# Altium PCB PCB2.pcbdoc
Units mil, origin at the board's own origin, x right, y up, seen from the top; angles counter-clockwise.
Board outline 3820.55 x 1645 mil, 2 copper layers (Top Layer, Bottom Layer); 41 components, 48 nets, 181 pads, 91 vias.
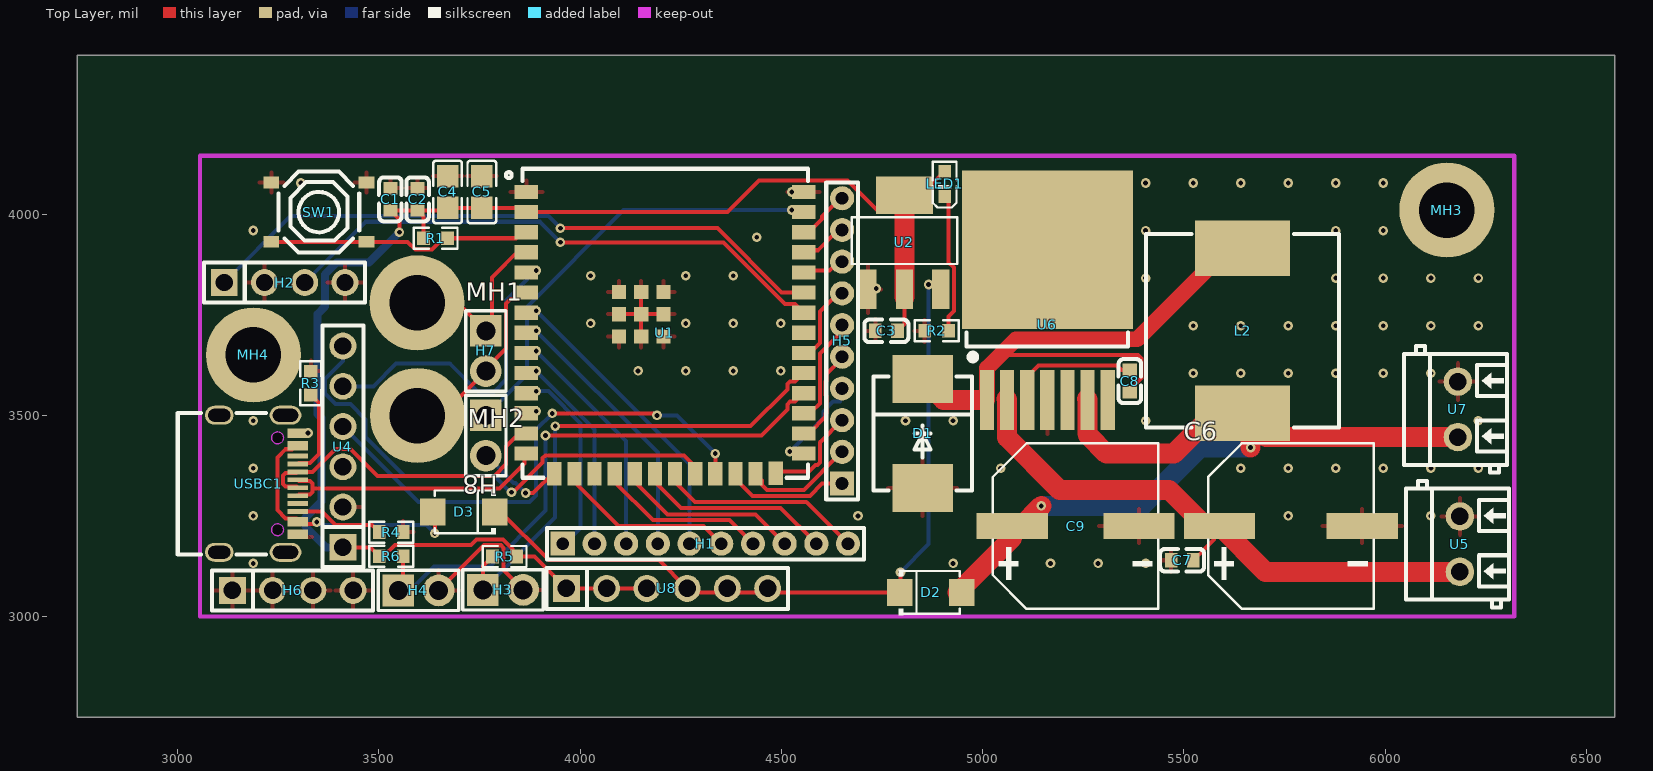
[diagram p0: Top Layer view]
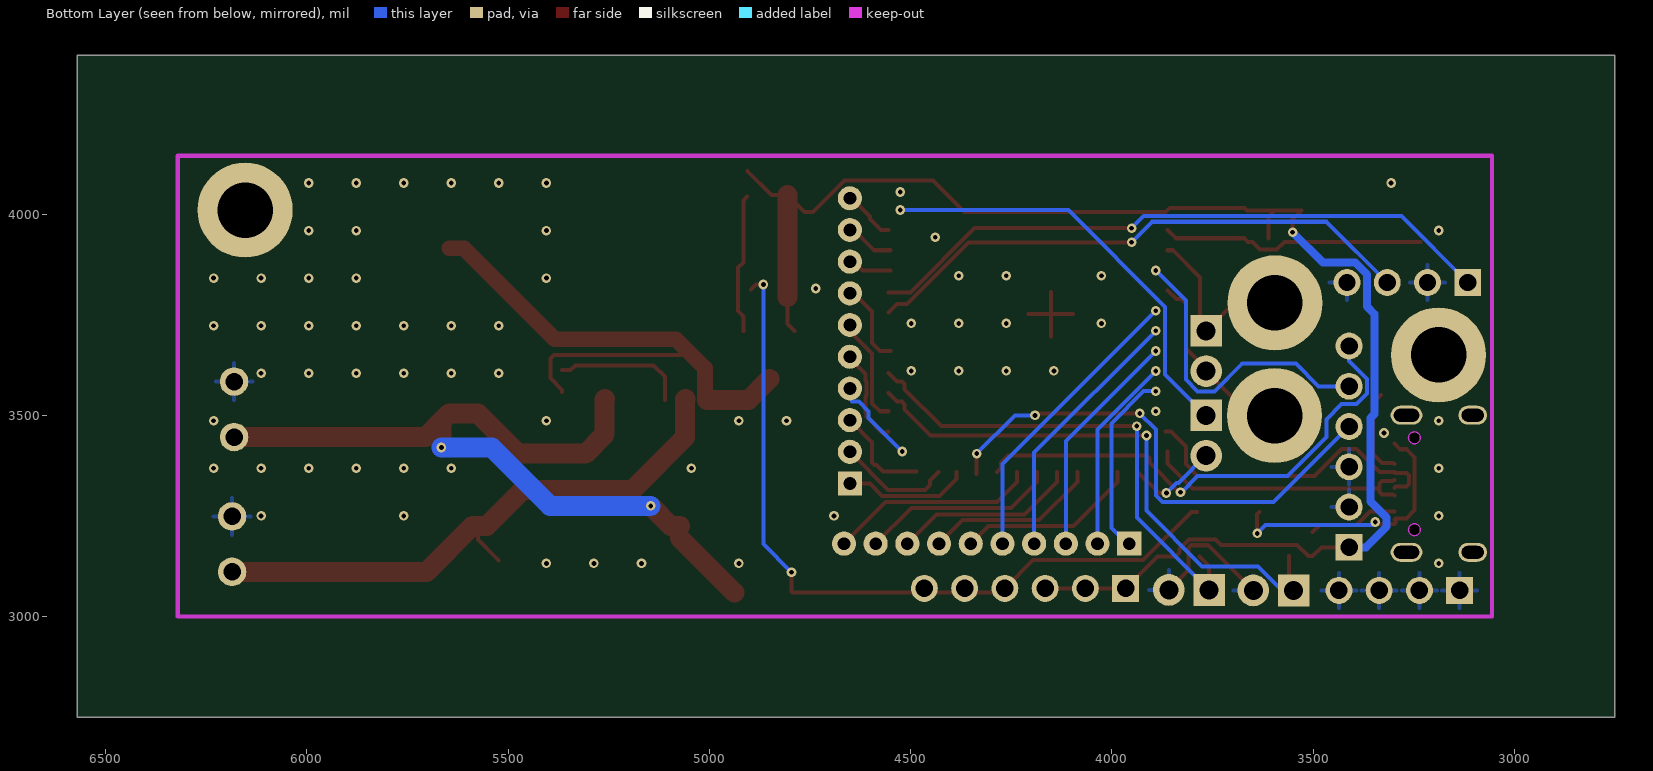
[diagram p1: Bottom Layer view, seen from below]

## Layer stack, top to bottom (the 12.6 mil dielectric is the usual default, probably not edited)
Top Layer: signal copper (thickness not stored)
Dielectric: dielectric 12.6, FR-4, Dk 4.8
Bottom Layer: signal copper (thickness not stored)

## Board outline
6570.55,2750 2750,2750 2750,4395 6570.55,4395

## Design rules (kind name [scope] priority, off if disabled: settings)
BoardOutlineClearance copperThickness1oz [All] p0: genericclearance=10 ignorepadtopadclearanceinfootprint=FALSE except(0: Arc-SplitContinuation Track-SplitContinuation SMDPad-SplitContinuation THPad-SplitContinuation Via-SplitContinuation Fill-SplitContinuation Poly-SplitContinuation Region-SplitContinuation Text-SplitContinuation; 6: Track-CutoutEdge SMDPad-CutoutEdge THPad-CutoutEdge Via-CutoutEdge Region-CutoutEdge; 11.8: Track-OutlineEdge SMDPad-OutlineEdge THPad-OutlineEdge Via-OutlineEdge Fill-OutlineEdge Region-OutlineEdge Poly-OutlineEdge Text-OutlineEdge Fill-CutoutEdge)
BoardOutlineClearance copperThickness2oz [All] p0: genericclearance=10 ignorepadtopadclearanceinfootprint=FALSE except(0: Arc-SplitContinuation Track-SplitContinuation SMDPad-SplitContinuation THPad-SplitContinuation Via-SplitContinuation Fill-SplitContinuation Poly-SplitContinuation Region-SplitContinuation Text-SplitContinuation; 6: Track-CutoutEdge SMDPad-CutoutEdge THPad-CutoutEdge Via-CutoutEdge Region-CutoutEdge; 11.8: Track-OutlineEdge SMDPad-OutlineEdge THPad-OutlineEdge Via-OutlineEdge Fill-OutlineEdge Region-OutlineEdge Poly-OutlineEdge Text-OutlineEdge Fill-CutoutEdge)
Clearance copperThickness1oz [(InNet('+3V') OR InNet('GND') OR InNet('$1N1546') OR InNet('LED_2') OR InNet('LED_1') OR InNet('$1N702') OR InNet('$1N2026') OR InNet('$1N2022') OR InNet('MIC_WS') OR InNet('SDA_1') OR InNet('USB_ESP_D-') OR InNet('USB_ESP_D+') OR InNet('RX') OR InNet('SCL_1') OR InNet('MIC_SDK') OR InNet('MIC_SCK') OR InNet('TX') OR InNet('+5V') OR InNet('USB_ESP_5V') OR InNet('+15V') OR InNet('$1N4882') OR InNet('$1N5299') OR InNet('TOUCH_1') OR InNet('TOUCH_2') OR InNet('IO7') OR InNet('IO15') OR InNet('IO16') OR InNet('IO17') OR InNet('IO18') OR InNet('IO46') OR InNet('IO10') OR InNet('IO11') OR InNet('IO12') OR InNet('IO13') OR InNet('IO47') OR InNet('IO48') OR InNet('IO45') OR InNet('IO0') OR InNet('IO35') OR InNet('IO36') OR InNet('BUTTON_2') OR InNet('BUTTON_1') OR InNet('IO39') OR InNet('IO40') OR InNet('RX0') OR InNet('TX0') OR InNet('IO2') OR InNet('5V_BUCK'))] p1: gap=7 ignorepadtopadclearanceinfootprint=FALSE except(4: Track-Track; 6: Track-SMDPad SMDPad-SMDPad Track-THPad SMDPad-THPad THPad-THPad Track-Via SMDPad-Via THPad-Via Via-Via SMDPad-Fill THPad-Fill Via-Fill Fill-Fill Track-Region SMDPad-Region THPad-Region Via-Region Region-Region Track-Poly SMDPad-Poly THPad-Poly Via-Poly Fill-Poly Region-Poly Poly-Poly Track-Text SMDPad-Text THPad-Text Via-Text Fill-Text Region-Text Poly-Text Text-Text; 6.9: Track-Hole SMDPad-Hole THPad-Hole Via-Hole Fill-Hole Region-Hole Poly-Hole Text-Hole Sheet-Hole; 11.8: Track-Fill Fill-Region Track-Sheet SMDPad-Sheet THPad-Sheet Via-Sheet Fill-Sheet Region-Sheet Poly-Sheet Text-Sheet)
Clearance copperThickness2oz [All] p1: gap=7 ignorepadtopadclearanceinfootprint=FALSE except(6: Track-SMDPad SMDPad-SMDPad Track-THPad SMDPad-THPad THPad-THPad Track-Via SMDPad-Via THPad-Via Via-Via SMDPad-Fill THPad-Fill Via-Fill Fill-Fill Track-Region SMDPad-Region THPad-Region Via-Region Region-Region Track-Poly SMDPad-Poly THPad-Poly Via-Poly Fill-Poly Region-Poly Poly-Poly Track-Text SMDPad-Text THPad-Text Via-Text Fill-Text Region-Text Poly-Text Text-Text; 6.9: Track-Hole SMDPad-Hole THPad-Hole Via-Hole Fill-Hole Region-Hole Poly-Hole Text-Hole Sheet-Hole; 8: Track-Track; 11.8: Track-Fill Fill-Region Track-Sheet SMDPad-Sheet THPad-Sheet Via-Sheet Fill-Sheet Region-Sheet Poly-Sheet Text-Sheet)
DiffPairsRouting differentialPair [All] p1: maxuncoupledlength=10 minlimit=6 maxlimit=6 mostfreqgap=6 toplayer_minwidth=5 toplayer_prefwidth=10 toplayer_maxwidth=100 bottomlayer_minwidth=5 bottomlayer_prefwidth=10 bottomlayer_maxwidth=100
PasteMaskExpansion pasteMaskExpansion [All] p1: expansion=0
PlaneConnect innerPlane [All] p1: planeconnectstyle=Relief reliefexpansion=20 reliefentries=4 reliefconductorwidth=10 reliefairgap=10
PolygonConnect copperRegion [All] p1: connectstyle=Relief reliefentries=4 reliefconductorwidth=10 polygonreliefangle="90 Angle" airgapwidth=10
RoutingVias viaSize [All] p1: viastyle="Through Hole" holewidth=12.0078 minholewidth=11.811 maxholewidth=248.0314 width=24.0158 minwidth=19.685 maxwidth=393.7008
SolderMaskExpansion solderMaskExpansion [All] p1: useseparateexpansions=TRUE expansion=2 expansionbottom=2
Width copperThickness1oz [All] p1: maxlimit=100 minlimit=5 preferedwidth=10
Width copperThickness2oz [All] p1: maxlimit=100 minlimit=8 preferedwidth=10

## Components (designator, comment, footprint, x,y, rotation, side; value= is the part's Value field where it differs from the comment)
C1 "CC0603KRX7R9BB104" C0603 3528.42,4036.76 r270 top
C2 "CL10A106KP8NNNC" C0603 3595.94,4036.76 r270 top
C3 "CL10A226MP8NUNE" C0603 4760.55,3710 r0 top
C4 "CL21B225KAFNNNE" C0805 3670.55,4055 r270 top
C5 "CL21B225KAFNNNE" C0805 3755.55,4055 r270 top
C6 "VMME1001H181MV" CAP-SMD_BD10.0-L10.3-W10.3-FD 5765.55,3225 r0 top
C7 "CC0603KRX7R9BB104" C0603 5495.55,3140 r0 top
C8 "CC0603KRX7R9BB103" C0603 5365.55,3585 r90 top
C9 "RVT1H271M1010" CAP-SMD_BD10.0-L10.3-W10.3-FD-1 5230.55,3225 r0 top
D1 "B540C-13-F" SMC_L7.1-W6.2-LS8.1-RD 4850.55,3455 r270 top
D2 "S2MF_C908416" SMAF_L3.5-W2.6-LS4.7-RD 4870.55,3060 r0 top
D3 "S2MF_C908416" SMAF_L3.5-W2.6-LS4.7-RD 3710.55,3260 r180 top
H1 "HX PZ2.0-1x10P ZZ" HDR-TH_10P-P2.00-V-M-1 4310.96,3181.24 r0 top
H2 "PZ254V-11-04P" HDR-TH_4P-P2.54-V-M 3265.55,3830 r0 top
H3 "PZ254V-11-02P" HDR-TH_2P-P2.54-V-M 3808.09,3066.24 r0 top
H4 "PZ254V-11-02P" HDR-TH_2P-P2.54-V-M 3598.09,3064.95 r0 top
H5 "HX PZ2.0-1x10P ZZ" HDR-TH_10P-P2.00-V-M-1 4650.55,3685 r90 top
H6 "PZ254V-11-04P" HDR-TH_4P-P2.54-V-M 3285.55,3065 r0 top
H7 "PZ254V-11-02P" HDR-TH_2P-P2.54-V-M 3765.55,3660 r270 top
H8 "PZ254V-11-02P" HDR-TH_2P-P2.54-V-M 3765.55,3450 r270 top
L2 "MSS1210-334KED" IND-SMD_L12.0-W12.0_SLH1207S100MTT 5645.55,3710 r90 top
LED1 "XL-1608UGC-04" LED0603-RD_GREEN 4905.55,4075 r90 top
MH1 "M3_Hole" M3_Hole 3594.66,3779.44 r0 top
MH2 "M3_Hole" M3_Hole 3595.57,3499.44 r0 top
MH3 "M3_Hole" M3_Hole 6153.11,4010.04 r0 top
MH4 "M3_Hole" M3_Hole 3188.11,3650.04 r0 top
R1 "RC0603FR-0710KL" R0603 3640.55,3940 r180 top
R2 "RC0603FR-07330RL" R0603 4885.55,3710 r0 top
R3 "RC0603FR-075K1L" R0603 3330.55,3580 r90 top
R4 "RC0603FR-075K1L" R0603 3530.55,3210 r180 top
R5 "RC0603FR-0710KL" R0603 3811.88,3149.3 r0 top
R6 "RC0603FR-0710KL" R0603 3530.55,3150 r180 top
SW1 "TS-1187A-B-A-B" SW-SMD_4P-L5.1-W5.1-P3.70-LS6.5-TL_H1.5 3350.55,4005 r180 top
U1 "ESP32-S3-WROOM-1U-N16R2" WIRELM-SMD_ESP32-S3-WROOM-1U 4210.55,3705 r0 top
U2 "AMS1117-3.3_C6186" SOT-223-3_L6.5-W3.4-P2.30-LS7.0-BR 4805.55,3930 r270 top
U4 "HB-PH3-25416PB2GOP" HDR-TH_6P-P2.54-V-M 3410.4,3422.24 r90 top
U5 "DB301V-3.5-2P-GN-S" CONN-TH_DB301V-3.5-2P-GN 6185.55,3180 r90 top
U6 "LM2678SX-5.0/NOPB" TO-263-7_L10.2-W8.6-P1.27-LS14.4-TL 5160.55,3725 r90 top
U7 "DB301V-3.5-2P-GN-S" CONN-TH_DB301V-3.5-2P-GN 6180.55,3515 r90 top
U8 "HB-PH3-25416PB2GOP" HDR-TH_6P-P2.54-V-M 4215.55,3070 r0 top
USBC1 "TYPE-C-31-M-12" USB-C_SMD-TYPE-C-31-M-12 3200.55,3330 r270 top

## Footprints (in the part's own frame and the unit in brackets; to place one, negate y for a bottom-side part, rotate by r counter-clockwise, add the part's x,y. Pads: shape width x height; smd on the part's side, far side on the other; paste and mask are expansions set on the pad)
C0603 [mm]
  rect 0.8x0.9 smd: 1(-0.7,0) 2(0.7,0)
  silkscreen extent -1.39,-0.71 1.39,0.71
C0805 [mm]
  rect 1.41x1.35 smd: 1(-1,0) 2(1,0)
  silkscreen extent -1.96,-0.9 1.96,0.9
CAP-SMD_BD10.0-L10.3-W10.3-FD [mm]
  rect 4.5x1.65 smd: 1(-4.5,0) 2(4.5,0)
  silkscreen extent -5.23,-5.23 5.23,5.23
CAP-SMD_BD10.0-L10.3-W10.3-FD-1 [mm]
  rect 4.5x1.65 smd: 1(-4,0) 2(4,0)
  silkscreen extent -5.23,-5.23 5.23,5.23
CONN-TH_DB301V-3.5-2P-GN [mm]
  round 1.8 hole 1.1: 1(-1.75,0) 2(1.75,0)
  silkscreen extent -4,-3.1 4,3.4
HDR-TH_2P-P2.54-V-M [mm]
  rect 2x2 hole 1.2: 1(-1.27,0)
  round 2 hole 1.2: 2(1.27,0)
  silkscreen extent -2.54,-1.27 2.54,1.27
HDR-TH_4P-P2.54-V-M [mm]
  rect 1.7x1.7 hole 1.1: 1(-3.81,0)
  round 1.7 hole 1.1: 2(-1.27,0) 3(1.27,0) 4(3.81,0)
  silkscreen extent -5.08,-1.27 5.08,1.27
HDR-TH_6P-P2.54-V-M [mm]
  rect 1.7x1.7 hole 1.1: 1(-6.35,0)
  round 1.7 hole 1.1: 2(-3.81,0) 3(-1.27,0) 4(1.27,0) 5(3.81,0) 6(6.35,0)
  silkscreen extent -7.6,-1.3 7.65,1.3
HDR-TH_10P-P2.00-V-M-1 [mil]
  rect 60x60 hole 31.5: 1(-354.33,0)
  round 60 hole 31.5: 2(-275.59,0) 3(-196.85,0) 4(-118.11,0) 5(-39.37,0) 6(39.37,0) 7(118.11,0) 8(196.85,0) 9(275.59,0) 10(354.33,0)
  silkscreen extent -394,-39 394,39
IND-SMD_L12.0-W12.0_SLH1207S100MTT [mm]
  rect 3.5x6 smd: 1(5.207,0) 2(-5.207,0)
  silkscreen extent -6.1,-6.1 6.1,6.1
LED0603-RD_GREEN [mm]
  rect 0.8x0.8 smd: 1(-0.799,-0.003) 2(0.799,0.003)
  silkscreen extent -1.49,-0.75 1.39,0.76
M3_Hole [mm]
  round 6 hole 3.5: 1(0,0)
R0603 [mil]
  rect 31.75x34.02 smd: 1(-29.66,0) 2(29.66,0)
  silkscreen extent -55,-26 55,26
SMAF_L3.5-W2.6-LS4.7-RD [mm]
  rect 1.6x1.7 smd: 1(-1.96,0) 2(1.96,0)
  silkscreen extent -2.01,-1.43 1.83,1.42
SMC_L7.1-W6.2-LS8.1-RD [mm]
  rect 3.03x3.82 smd: 1(-3.435,0) 2(3.435,0)
  silkscreen extent -3.6,-3.11 3.6,3.11
SOT-223-3_L6.5-W3.4-P2.30-LS7.0-BR [mm]
  rect 2.5x1.1 smd: 1(2.97,-2.3) 2(2.97,0) 3(2.97,2.3)
  rect 2.34x3.6 smd: 4(-2.97,0)
  silkscreen extent -1.57,-3.33 1.37,3.33
SW-SMD_4P-L5.1-W5.1-P3.70-LS6.5-TL_H1.5 [mm]
  rect 1x0.75 smd: 1(-3,1.875) 2(3,1.875) 3(-3,-1.875) 4(3,-1.875)
  silkscreen extent -2.55,-2.55 2.55,2.55
TO-263-7_L10.2-W8.6-P1.27-LS14.4-TL [mm]
  rect 3.81x0.9 smd: 1(-4.743,3.81) 2(-4.743,2.54) 3(-4.743,1.27) 4(-4.743,0) 5(-4.743,-1.27) 6(-4.743,-2.54) 7(-4.743,-3.81)
  rect 10x10.8 smd: 8(4.743,0)
  silkscreen extent -2.23,-5.09 -0.49,5.11
USB-C_SMD-TYPE-C-31-M-12 [mm]
  oval 1.2x2 hole 0.8 slot 1.6 at 90 deg: 0(-4.325,1.706) 1(4.325,1.706)
  oval 1.2x1.8 hole 0.8 slot 1.4 at 90 deg: 2(4.325,-2.474) 3(-4.325,-2.474)
  rect 0.3x1.3 smd: A1(-3.35,2.474) A4(-2.55,2.474) A5(-1.25,2.474) A6(-0.25,2.474) A7(0.25,2.474) A8(1.25,2.474) A9(2.55,2.474) A12(3.35,2.474) B1(3.05,2.474) B4(2.25,2.474) B5(1.75,2.474) B6(0.75,2.474) B7(-0.75,2.474) B8(-1.75,2.474) B9(-2.25,2.474) B12(-3.05,2.474)
  Board Outline Layer circle w0.005: c-2.9,1.206 r0.375
  Board Outline Layer circle w0.005: c2.9,1.206 r0.375
  Board Outline Layer region: -2.9,1.581 -2.737,1.544 -2.607,1.439 -2.534,1.289 -2.534,1.122 -2.607,0.972 -2.737,0.868 -2.9,0.831 -2.9,0.831 -3.063,0.868 -3.193,0.972 -3.266,1.122 -3.266,1.289 -3.193,1.439 -3.063,1.544 -2.9,1.581
  Board Outline Layer region: 2.9,1.581 3.063,1.544 3.193,1.439 3.266,1.289 3.266,1.122 3.193,0.972 3.063,0.868 2.9,0.831 2.9,0.831 2.737,0.868 2.607,0.972 2.534,1.122 2.534,1.289 2.607,1.439 2.737,1.544 2.9,1.581
  Multi-Layer board cut-out: -2.9,1.581 -2.737,1.544 -2.607,1.439 -2.534,1.289 -2.534,1.122 -2.607,0.972 -2.737,0.868 -2.9,0.831 -2.9,0.831 -3.063,0.868 -3.193,0.972 -3.266,1.122 -3.266,1.289 -3.193,1.439 -3.063,1.544 -2.9,1.581
  Multi-Layer board cut-out: 2.9,1.581 3.063,1.544 3.193,1.439 3.266,1.289 3.266,1.122 3.193,0.972 3.063,0.868 2.9,0.831 2.9,0.831 2.737,0.868 2.607,0.972 2.534,1.122 2.534,1.289 2.607,1.439 2.737,1.544 2.9,1.581
  silkscreen extent -4.47,-5.09 4.47,0.49
WIRELM-SMD_ESP32-S3-WROOM-1U [mm]
  rect 1.5x0.9 smd: 1(-8.75,8.895) 2(-8.75,7.625) 3(-8.75,6.355) 4(-8.75,5.085) 5(-8.75,3.815) 6(-8.75,2.545) 7(-8.75,1.275) 8(-8.75,0.005) 9(-8.75,-1.265) 10(-8.75,-2.535) 11(-8.75,-3.805) 12(-8.75,-5.075) 13(-8.75,-6.345) 14(-8.75,-7.615) 27(8.75,-7.615) 28(8.75,-6.345) 29(8.75,-5.075) 30(8.75,-3.805) 31(8.75,-2.535) 32(8.75,-1.265) 33(8.75,0.005) 34(8.75,1.275) 35(8.75,2.545) 36(8.75,3.815) 37(8.75,5.085) 38(8.75,6.355) 39(8.75,7.625) 40(8.75,8.895)
  rect 0.9x1.5 smd: 15(-6.985,-8.895) 16(-5.715,-8.895) 17(-4.445,-8.895) 18(-3.175,-8.895) 19(-1.905,-8.895) 20(-0.635,-8.895) 21(0.635,-8.895) 22(1.905,-8.895) 23(3.175,-8.895) 24(4.445,-8.895) 25(5.715,-8.895) 26(6.985,-8.865)
  rect 0.9x0.9 smd: 41(-2.9,-0.225) 41(-2.9,1.175) 41(-2.9,2.575) 41(-1.5,-0.225) 41(-1.5,1.175) 41(-1.5,2.575) 41(-0.1,-0.225) 41(-0.1,1.175) 41(-0.1,2.575)
  silkscreen extent -10.04,-9.14 9.02,10.36

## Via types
v1: diameter 24.02, hole 12.01, Top Layer to Bottom Layer, 91 vias

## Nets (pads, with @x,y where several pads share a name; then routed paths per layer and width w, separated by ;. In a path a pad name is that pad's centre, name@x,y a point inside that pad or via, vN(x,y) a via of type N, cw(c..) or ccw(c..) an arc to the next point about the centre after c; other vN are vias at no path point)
5V_BUCK: C9.1 D2.2 L2.2 U6.6 U7.1 | length 2024
  Top Layer w50: D2.2@4937.72,3060 C9.1@5073.07,3195.35 ; C9.1 5095.55,3225 v1(5145.55,3275) ; U6.6@5259.34,3540.43 5260.64,3539.13 5260.64,3454.91 5261.85,3453.7 5261.85,3450.42 5307.27,3405 5474.84,3405 5574.84,3505 L2.2 L2.2@5665.55,3485 ; v1(5665.55,3420) L2.2@5665.55,3485 ; U7.1 5704.45,3446.11 L2.2@5665.55,3485
  Bottom Layer w50: v1(5145.55,3275) 5395.55,3275 5540.55,3420 v1(5665.55,3420)
$1N702: R1.1 SW1.1 SW1.2 U1.3 | length 656.5
  Top Layer w10: SW1.2 SW1.1 3571.29,3931.18 3590.47,3912.01 3631.32,3912.01 3650.49,3931.18 3661.39,3931.18 R1.1 3840.87,3940 U1.3@3861.06,3960.2
$1N1546: LED1.1 R2.2 | length 348.7
  Top Layer w10: LED1.1 4915.21,4034 4915.21,3880.36 4928.74,3866.84 4928.74,3759.31 4915.21,3745.78 R2.2
$1N2022: R4.2 USBC1.B5 | length 224.1
  Top Layer w10: USBC1.B5 3358.68,3261.1 3391.99,3227.79 3483.1,3227.79 R4.2
$1N2026: R3.1 USBC1.A5 | length 217.2
  Top Layer w10: USBC1.A5 3300.76,3382.01 3328.1,3382.01 3350.55,3404.46 3350.55,3530.34 R3.1
$1N4882: C8.2 U6.3 | length 329.6
  Top Layer w10: U6.3 5110.55,3596.51 5138.29,3624.24 5332.82,3624.24 5344.5,3612.56 C8.2
$1N5299: C8.1 D1.1 L2.1 U6.1 | length 1443.2
  Top Layer w10: 5064.05,3650 5385.55,3650 5394.25,3641.3 5394.25,3592.26 5365.55,3563.56 C8.1
  Top Layer w39.4: U6.1 U6.1 5010.63,3617.37 5082.47,3689.21 5383.79,3689.21 5609.58,3915 L2.1
  Top Layer w50: D1.1 4902.53,3538.26 U6.1@5005.33,3538.26
+3V: C1.2 C2.2 C3.2 C4.2 C5.2 LED1.2 R1.2 R5.2 R6.2 U1.2 U2.2 U2.4 U4.1 U8.1 U8.2 U8.3 | length 3816.3
  Top Layer w10: U4.1@3395.4,3172.24 3478.65,3172.24 R6.2 3511.8,3150 3539.79,3177.99 3728.45,3177.99 3741.77,3191.31 3808.45,3191.31 3831.54,3168.22 3831.54,3159.3 R5.2 3886.25,3149.3 U8.1 U8.2 U8.3 ; v1(3550.55,3955) 3550.55,3987.06 C1.2 C2.2 ; R1.2 3610.89,3994.25 C2.2 ; U1.2@3861.06,4010.2 3855.63,4015.63 C5.2 C4.2 3664.12,4009.2 C2.2 ; U1.2 4365.75,4005.2 4444.45,4083.9 4663.95,4083.9 4742.65,4005.2 4763.82,4005.2 U2.4 4845.87,4046.93 LED1.2 ; C3.2 4805.55,3727.44 U2.2@4805.55,3794.21
  Top Layer w50: U2.2@4805.55,3794.21 U2.2 U2.4
  Bottom Layer w20: U4.1 3368.73,3172.24 3317.56,3223.41 3317.56,3246.59 3357.15,3286.18 3357.15,3493.41 3346.94,3503.62 3346.94,3751.38 3366.1,3770.55 3366.1,3850.48 3395.07,3879.45 3475,3879.45 v1(3550.55,3955)
+5V: D2.1 D3.1 U2.3 U8.4 U8.5 U8.6 | length 1918.9
  Top Layer w10: D3.1 3802.33,3260 3922.08,3140.25 4195.3,3140.25 U8.4 4275.55,3060 D2.1 4795.55,3062.16 v1(4795.55,3110) ; v1(4865.55,3825) 4884.18,3825 U2.3
  Bottom Layer w10: v1(4795.55,3110) 4865.55,3180 v1(4865.55,3825)
+15V: C6.1 C7.2 U5.1 U6.2 | length 1465.6
  Top Layer w10: C7.2 5574.79,3191.68 C6.1@5574.79,3225
  Top Layer w50: U6.2@5059.34,3540.43 5060.64,3539.13 5060.64,3444.91 5190.55,3315 5462.91,3315 5552.91,3225 5574.79,3225 C6.1 5702.29,3111.11 U5.1
BUTTON_1: H3.1 R5.1 U1.31 | length 1253.9
  Top Layer w10: H3.1 3758.09,3125.18 R5.1 ; v1(3937.79,3473.22) 4423.07,3473.22 4514.53,3564.68 4514.53,3577.46 4520.97,3583.9 4533.74,3583.9 U1.31
  Bottom Layer w10: H3.1 3937.79,3245.93 v1(3937.79,3473.22)
BUTTON_2: H4.1 R6.1 U1.30 | length 1417.1
  Top Layer w10: H4.1 3560.21,3077.07 R6.1 ; v1(3913.58,3450) 4449.85,3450 4514.53,3514.68 4514.53,3527.46 4520.97,3533.9 4533.74,3533.9 U1.30
  Bottom Layer w10: H4.1 3576.88,3064.95 3636.94,3125 3775.55,3125 3913.58,3263.03 v1(3913.58,3450)
GND: C1.1 C2.1 C3.1 C4.1 C5.1 C6.2 C7.1 C9.2 D1.2 H2.2 H2.4 H3.2 H4.2 H6.1 H6.2 H6.3 H6.4 R2.1 R3.2 R4.1 SW1.3 SW1.4 U1.1 U1.40 U1.41 U2.1 U4.2 U4.3 U5.2 U6.4 U7.2 USBC1.A1 USBC1.A12 USBC1.B1 USBC1.B12 | length 555.6
  Top Layer w10: H4.2 3760.44,3177.29 3802.64,3177.29 3809.08,3170.86 3809.08,3115.25 H3.2 ; U1.41@4096.37,3751.26 U1.41@4151.49,3751.26 ; U1.41@4151.49,3696.14 U1.41@4151.49,3751.26 ; U1.41@4151.49,3806.38 U1.41@4151.49,3751.26 ; U1.41@4206.61,3751.26 U1.41@4151.49,3751.26
  other v1: 3187.76,3132.21 4926.4,3132.21 5168.5,3132.21 5286.61,3132.21 5404.72,3132.21 3187.76,3250.32 4690.18,3250.32 5759.05,3250.32 6113.38,3250.32 3187.76,3368.43 5044.51,3368.43 5640.94,3368.43 5759.05,3368.43 5877.16,3368.43 5995.27,3368.43 6113.38,3368.43 6231.49,3368.43 3323.55,3455.98 3187.76,3486.54 4808.29,3486.54 4926.4,3486.54 5404.72,3486.54 6231.49,3486.54 5522.83,3604.65 5640.94,3604.65 5759.05,3604.65 5877.16,3604.65 5995.27,3604.65 6113.38,3604.65 4143.88,3610.43 4261.99,3610.43 4380.1,3610.43 4498.21,3610.43 5522.83,3722.76 5640.94,3722.76 5759.05,3722.76 5877.16,3722.76 5995.27,3722.76 6113.38,3722.76 6231.49,3722.76 4025.77,3728.54 4261.99,3728.54 4380.1,3728.54 4498.21,3728.54 4735.55,3815 5404.72,3840.87 5877.16,3840.87 5995.27,3840.87 6113.38,3840.87 6231.49,3840.87 4025.77,3846.65 4261.99,3846.65 4380.1,3846.65 4438.38,3942.41 3187.76,3959.3 5404.72,3958.98 5877.16,3958.98 5995.27,3958.98 4525.55,4055 3305.87,4077.41 5404.72,4077.09 5522.83,4077.09 5640.94,4077.09 5759.05,4077.09 5877.16,4077.09 5995.27,4077.09
IO0: H5.4 U1.27 | length 223.1
  Bottom Layer w10: v1(4520.55,3410) 4604.57,3494.02 4604.57,3510.13 4628.58,3534.13 4644.69,3534.13 4645.55,3535 H5.4@4645.55,3571.89
IO2: H5.10 U1.38 | length 134.1
  Top Layer w10: U1.38@4555.04,3960.2 4572.82,3960.2 4600.55,3987.93 4600.55,3994.33 H5.10@4650.55,4044.33
IO7: H1.5 U1.7 | length 736.6
  Bottom Layer w10: v1(3890.55,3760) 4271.59,3378.96 H1.5
IO10: H1.7 U1.18 | length 432
  Top Layer w10: U1.18@4085.55,3359.8 4085.55,3335 4180.55,3240 4370.31,3240 H1.7
IO11: H1.8 U1.19 | length 460.8
  Top Layer w10: U1.19@4135.55,3359.8 4135.55,3335 4216.54,3254.02 4435.03,3254.02 H1.8
IO12: H1.9 U1.20 | length 489.5
  Top Layer w10: U1.20@4185.55,3359.8 4185.55,3335 4250.55,3270 4497.79,3270 H1.9
IO13: H1.10 U1.21 | length 518.2
  Top Layer w10: U1.21@4235.55,3359.8 4235.55,3335 4285.55,3285 4561.53,3285 H1.10
IO15: H1.4 U1.8 | length 654
  Bottom Layer w10: v1(3890.55,3710) 4192.85,3407.7 H1.4
IO16: H1.3 U1.9 | length 571.4
  Bottom Layer w10: v1(3890.55,3660) 4114.11,3436.44 H1.3
IO17: H1.2 U1.10 | length 488.7
  Bottom Layer w10: v1(3890.55,3610) 4035.37,3465.18 H1.2
IO18: H1.1 U1.11 | length 463.1
  Bottom Layer w10: v1(3890.55,3560) 3920.73,3560 4000.55,3480.18 4000.55,3220.16 3961.63,3181.24 H1.1
IO35: H5.5 U1.28 | length 239.6
  Top Layer w10: U1.28@4555.04,3460.2 4557.54,3457.7 4570.32,3457.7 4609.57,3496.94 4609.57,3505.13 4612.07,3507.63 4612.07,3547.41 4609.57,3549.91 4609.57,3583.87 4612.07,3586.37 4612.07,3602.15 4650.55,3640.63 H5.5
IO36: H5.6 U1.29 | length 270.9
  Top Layer w10: U1.29@4555.04,3510.2 4575.75,3510.2 4595.55,3530 4595.55,3653.59 4650.55,3708.59 H5.6@4650.55,3729.37
IO39: H5.7 U1.32 | length 202.5
  Top Layer w10: U1.32@4550.04,3660.2 4575.75,3660.2 4595.55,3680 4595.55,3758.11 H5.7@4645.55,3808.11
IO40: U1.33
IO45: H5.3 U1.26 | length 247.1
  Top Layer w10: U1.26@4485.55,3360.99 4568.61,3360.99 4584.12,3376.49 4589.12,3376.49 4595.55,3382.93 4595.55,3433.15 H5.3
IO46: H1.6 U1.16 | length 453.3
  Top Layer w10: U1.16@3985.55,3359.8 3985.55,3335 4095.55,3225 4306.57,3225 H1.6
IO47: H5.1 U1.24 | length 312.9
  Top Layer w10: U1.24@4385.55,3359.8 4385.55,3342.03 4427.58,3300 4570.55,3300 4601.22,3330.67 H5.1
IO48: H5.2 U1.25 | length 287
  Top Layer w10: U1.25@4430.55,3359.8 4451.85,3338.51 4451.85,3326.91 4463.76,3315 4555.55,3315 4645.55,3405 H5.2@4645.55,3414.41
LED_1: H2.1 U1.35 | length 1586.5
  Top Layer w10: v1(3950.55,3965) 4340.55,3965 4500.36,3805.2 U1.35
  Bottom Layer w10: H2.1 3280.55,3995 3920.55,3995 v1(3950.55,3965)
LED_2: H2.3 U1.34 | length 1395.6
  Top Layer w10: v1(3950.55,3930) 4355.73,3930 4509.24,3776.49 4533.74,3776.49 U1.34
  Bottom Layer w10: H2.3 3466.54,3980.98 3899.57,3980.98 v1(3950.55,3930)
MIC_SCK: U1.23 U4.4 | length 1282.2
  Top Layer w10: v1(3930.55,3505) 4185.55,3505 v1(4190.55,3500) ; U1.23 v1(4335.55,3405)
  Bottom Layer w10: U4.4 3598.44,3284.2 3873.86,3284.2 3890.55,3300.89 3890.55,3465 v1(3930.55,3505) ; v1(4190.55,3500) 4240.55,3500 v1(4335.55,3405)
MIC_SDK: U1.22 U4.6 | length 1252.2
  Top Layer w10: v1(3829.34,3308.79) 3832.43,3308.79 3906.57,3382.93 3906.57,3393.6 3913.29,3400.32 4257.82,3400.32 4275.55,3382.58 4275.55,3369.8 U1.22@4285.55,3359.8
  Bottom Layer w10: U4.6 3410.4,3635.1 3365.95,3590.65 3365.95,3553.83 3391.99,3527.79 3428.81,3527.79 3466.47,3490.13 3466.47,3445.97 3562.8,3349.65 3786.41,3349.65 3827.27,3308.79 v1(3829.34,3308.79)
MIC_WS: U1.5 U4.5 | length 771.4
  Bottom Layer w10: U4.5 3485.8,3572.24 3542.1,3628.54 3675.8,3628.54 3744.7,3559.65 3786.41,3559.65 3815.91,3589.14 3815.91,3785.35 v1(3890.55,3860)
RX: H8.2 U1.15 | length 230.2
  Top Layer w10: v1(3864.34,3307.2) 3882.94,3307.2 U1.15@3935.55,3359.8
  Bottom Layer w10: H8.2 3766.53,3400 3834.76,3331.78 3838.86,3331.78 3852.33,3318.31 3853.22,3318.31 v1(3864.34,3307.2)
RX0: H5.8 U1.36 | length 106.6
  Top Layer w10: U1.36@4550.04,3860.2 4618.9,3860.2 H5.8@4645.55,3886.85
SCL_1: U1.17
SDA_1: U1.12
  other v1: 3890.55,3510
TOUCH_1: H7.1 MH1.1 U1.4 | length 446.9
  Top Layer w10: MH1.1 3696.11,3779.44 H7.1 3780.55,3725 3780.55,3842.46 3848.28,3910.2 U1.4@3861.06,3910.2
TOUCH_2: H7.2 MH2.1 U1.6 | length 463
  Top Layer w10: MH2.1 3655,3499.44 H7.2 3765.55,3615.73 3815.91,3666.08 3815.91,3777.82 3826.99,3788.9 3839.76,3788.9 U1.6@3861.06,3810.2
TX: H8.1 U1.39 | length 1069.4
  Bottom Layer w10: H8.1 3867.56,3602.01 3867.56,3769.52 4108.04,4010 v1(4525.55,4010)
TX0: H5.9 U1.37 | length 118.5
  Top Layer w10: U1.37@4550.04,3910.2 4590.16,3910.2 H5.9@4645.55,3965.59
USB_ESP_5V: D3.2 USBC1.A4 USBC1.A9 USBC1.B4 USBC1.B9 | length 681.8
  Top Layer w10: USBC1.B4 USBC1.B4@3295.17,3244.21 ; USBC1.A4 3283.36,3415.79 3267.82,3415.79 3247.37,3395.34 3247.37,3264.66 3267.82,3244.21 USBC1.B4@3295.17,3244.21 ; v1(3345.55,3235) 3340.15,3229.6 USBC1.A9 3295.17,3232.39 USBC1.B4@3295.17,3244.21 ; D3.2 3638.66,3254.73 v1(3638.66,3206.8)
  Bottom Layer w10: v1(3345.55,3235) 3352.76,3227.79 3617.67,3227.79 v1(3638.66,3206.8)
USB_ESP_D+: U1.14 USBC1.A6 USBC1.B6 | length 683.6
  Top Layer w10: USBC1.B6 3300.76,3303.27 3328.1,3303.27 3334.53,3309.7 3334.53,3318.53 ; USBC1.A6 3300.75,3337.05 3328.1,3337.05 3334.53,3330.62 3334.53,3318.53 ; U1.14@3861.06,3410.2 3861.06,3380.51 3799.08,3318.53 3334.53,3318.53
USB_ESP_D-: U1.13 USBC1.A7 USBC1.B7 | length 792.6
  Top Layer w10: USBC1.A7 3295.17,3322.95 3267.82,3322.95 3261.39,3329.38 3261.39,3350.3 3267.82,3356.73 3295.16,3356.73 USBC1.B7 3334.83,3359.53 3391.99,3416.69 3428.81,3416.69 3495.85,3349.65 3786.41,3349.65 3815.91,3379.14 3815.91,3422.82 3853.28,3460.2 U1.13@3866.06,3460.2
pads on no net: MH3.1 MH4.1 U6.5 U6.7 U6.8 USBC1.0 USBC1.1 USBC1.2 USBC1.3 USBC1.A8 USBC1.B8

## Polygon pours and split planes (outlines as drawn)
GND on Top Layer (solid, remove dead copper, pour order 0): 3055.55,4145 6320.55,4145 6320.55,3000 3055.55,3000
GND on Bottom Layer (solid, remove dead copper, pour order 2): 3055.55,4145 6320.55,4145 6320.55,3000 3055.55,3000

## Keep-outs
Board Outline Layer:
  lines w10: 3055.55,3000 6320.55,3000 6320.55,4145 3055.55,4145 3055.55,3000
